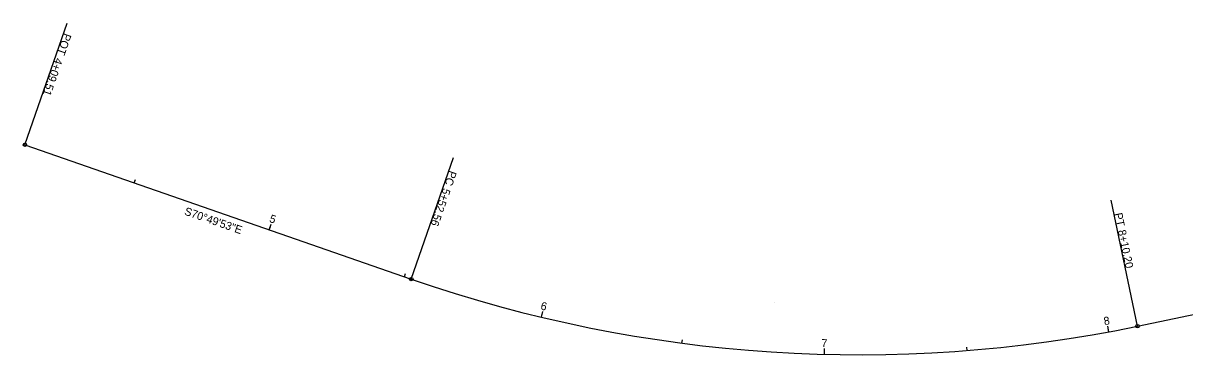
# Model space of a CAD drawing. Extents: x 2196614 to 2198263, y 660890 to 662319.
# Drawn here: x 2196614.1 to 2197020.4, y 661916 to 662031.9 of the extents above; entities that cross this region are included whole.
import ezdxf

# ---------------------------------------------------------------- set-up
doc = ezdxf.new("R2010")
doc.units = 0
for name, color, linetype in [('Default', 7, 'Continuous'), ('GE_X_Alignment', 7, 'Continuous'), ('GE_X_Alignment_1000_Stations', 7, 'Continuous'), ('GE_X_Alignment_100_Stations', 7, 'Continuous'), ('GE_X_Alignment_500_Stations', 7, 'Continuous')]:
    doc.layers.add(name, color=color, linetype=linetype)

msp = doc.modelspace()

# ---------------------------------------------------------------- linework, layer by layer
at = {"layer": 'Default'}
for centre in [(2196614.72, 661989.41), (2196614.72, 661989.41), (2196614.72, 661989.41), (2196682.28, 661965.92), (2196682.28, 661965.92), (2196682.28, 661965.92), (2196682.28, 661965.92), (2196682.28, 661965.92), (2196682.28, 661965.92), (2196700.19, 661959.7), (2196700.19, 661959.7), (2196749.84, 661942.44), (2196749.84, 661942.44), (2196749.84, 661942.44), (2196876.84, 661934.2), (2196876.84, 661934.2), (2196876.84, 661934.2), (2196795.35, 661929.11), (2197003.84, 661925.97), (2197003.84, 661925.97), (2197003.84, 661925.97), (2196993.82, 661924), (2196894.32, 661916.13)]:
    msp.add_circle(centre, 0.0000833, dxfattribs=at)
at = {"layer": 'GE_X_Alignment'}
for p, q in [((2196614.72, 661989.41), (2196749.84, 661942.44)), ((2197003.84, 661925.97), (2197238.07, 661974.69))]:
    msp.add_line(p, q, dxfattribs=at)
msp.add_arc((2196906.62, 662393.43), 477.46, 250.8314, 281.7486, dxfattribs=at)
at = {"layer": 'GE_X_Alignment_1000_Stations'}
for p, q in [((2196614.72, 661989.41), (2196629.5, 662031.92)), ((2196749.84, 661942.44), (2196764.62, 661984.94)), ((2197003.84, 661925.97), (2196994.67, 661970.03)), ((2196700.19, 661959.7), (2196700.59, 661960.83))]:
    msp.add_line(p, q, dxfattribs=at)
for centre in [(2196614.72, 661989.41), (2196749.84, 661942.44), (2197003.84, 661925.97)]:
    msp.add_circle(centre, 0.6, dxfattribs=at)
at = {"layer": 'GE_X_Alignment_100_Stations'}
for p, q in [((2196614.72, 661989.41), (2196629.5, 662031.92)), ((2196749.84, 661942.44), (2196764.62, 661984.94)), ((2196652.97, 661976.12), (2196653.36, 661977.25)), ((2197003.84, 661925.97), (2196994.67, 661970.03)), ((2196700.19, 661959.7), (2196700.85, 661961.59)), ((2196747.42, 661943.28), (2196747.81, 661944.41)), ((2196795.35, 661929.11), (2196795.81, 661931.06)), ((2196993.82, 661924), (2196993.46, 661925.96)), ((2196844.49, 661920.03), (2196844.65, 661921.22)), ((2196894.32, 661916.13), (2196894.37, 661918.12)), ((2196944.28, 661917.45), (2196944.18, 661918.65))]:
    msp.add_line(p, q, dxfattribs=at)
for centre in [(2196614.72, 661989.41), (2196749.84, 661942.44), (2197003.84, 661925.97)]:
    msp.add_circle(centre, 0.6, dxfattribs=at)
at = {"layer": 'GE_X_Alignment_500_Stations'}
for p, q in [((2196614.72, 661989.41), (2196629.5, 662031.92)), ((2196749.84, 661942.44), (2196764.62, 661984.94)), ((2197003.84, 661925.97), (2196994.67, 661970.03)), ((2196700.19, 661959.7), (2196700.85, 661961.59)), ((2196795.35, 661929.11), (2196795.63, 661930.28)), ((2196993.82, 661924), (2196993.6, 661925.18)), ((2196894.32, 661916.13), (2196894.35, 661917.32))]:
    msp.add_line(p, q, dxfattribs=at)
for centre in [(2196614.72, 661989.41), (2196749.84, 661942.44), (2197003.84, 661925.97)]:
    msp.add_circle(centre, 0.6, dxfattribs=at)

# ---------------------------------------------------------------- texts
at = {"layer": 'GE_X_Alignment_1000_Stations'}
for s, rotation, p in [('POT', 250.8314, (2196628.4, 662028.63)), ('4+09.51', 250.8314, (2196625.4, 662020)), ('PC', 250.8314, (2196763.15, 661980.59)), ('5+52.56', 250.8314, (2196761.01, 661974.43)), ('S70°49\'53"E', 340.8314, (2196670.25, 661965.03)), ('PT', 281.7486, (2196995.7, 661965.32)), ('8+10.20', 281.7486, (2196996.94, 661959.36))]:
    msp.add_text(s, height=2.8, rotation=rotation, dxfattribs=at).set_placement(p)
at = {"layer": 'GE_X_Alignment_100_Stations'}
for s, rotation, p in [('POT', 250.8314, (2196628.4, 662028.63)), ('4+09.51', 250.8314, (2196625.4, 662020)), ('PC', 250.8314, (2196763.15, 661980.59)), ('5+52.56', 250.8314, (2196761.01, 661974.43)), ('S70°49\'53"E', 340.8314, (2196670.25, 661965.03)), ('PT', 281.7486, (2196995.7, 661965.32)), ('5', 340.8314, (2196699.97, 661962.47)), ('8+10.20', 281.7486, (2196996.94, 661959.36)), ('6', 346.5238, (2196794.86, 661931.85)), ('8', 10.5241, (2196992.27, 661926.3)), ('7', 358.524, (2196893.22, 661918.65))]:
    msp.add_text(s, height=2.8, rotation=rotation, dxfattribs=at).set_placement(p)
at = {"layer": 'GE_X_Alignment_500_Stations'}
for s, rotation, p in [('POT', 250.8314, (2196628.4, 662028.63)), ('4+09.51', 250.8314, (2196625.4, 662020)), ('PC', 250.8314, (2196763.15, 661980.59)), ('5+52.56', 250.8314, (2196761.01, 661974.43)), ('S70°49\'53"E', 340.8314, (2196670.25, 661965.03)), ('PT', 281.7486, (2196995.7, 661965.32)), ('5', 340.8314, (2196699.97, 661962.47)), ('8+10.20', 281.7486, (2196996.94, 661959.36))]:
    msp.add_text(s, height=2.8, rotation=rotation, dxfattribs=at).set_placement(p)

doc.saveas('drawing.dxf')
